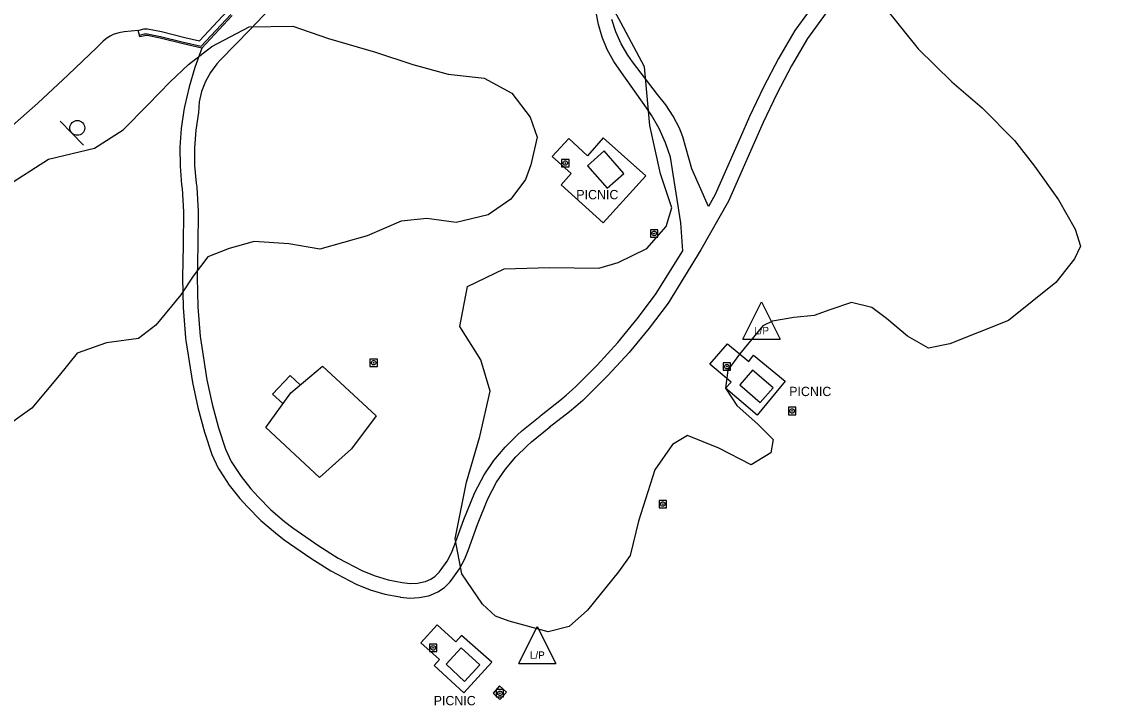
# Model space of a CAD drawing. Extents: x 2161152 to 2175754, y 602179 to 617749.
# Drawn here: x 2163221.4 to 2163512.2, y 604952.2 to 605136.2 of the extents above; entities that cross this region are included whole.
import ezdxf

# ---------------------------------------------------------------- set-up
doc = ezdxf.new("R2010")
doc.units = 0
for name, color, linetype in [('RD_EX_Bldg', 7, 'Continuous'), ('RD_EX_BldgApp_Sign', 7, 'Continuous'), ('RD_EX_Conc_Curb', 7, 'Continuous'), ('RD_EX_Conc_Gutter', 7, 'Continuous'), ('RD_EX_Conc_Sidewalk', 7, 'Continuous'), ('RD_EX_Conc_Slab', 7, 'Continuous'), ('RD_EX_Misc', 7, 'Continuous'), ('RD_EX_Misc_Golf_Cartpath', 7, 'Continuous'), ('RD_EX_Parking_Conc', 7, 'Continuous'), ('RD_EX_UT', 7, 'Continuous'), ('RD_EX_VEG', 7, 'Continuous')]:
    doc.layers.add(name, color=color, linetype=linetype)

msp = doc.modelspace()

# ---------------------------------------------------------------- linework, layer by layer
at = {"layer": 'RD_EX_Bldg'}
msp.add_lwpolyline([(2163287.04, 605026.92), (2163293.79, 605036.25), (2163302.3, 605043.44), (2163316.78, 605030.11), (2163310.1, 605021.2), (2163301.49, 605013.52), (2163287.04, 605026.92)], dxfattribs=at)
at = {"layer": 'RD_EX_BldgApp_Sign'}
msp.add_line((2163231.72, 605109.37), (2163238.02, 605102.94), dxfattribs=at)
msp.add_circle((2163236.33, 605107.56), 2, dxfattribs=at)
at = {"layer": 'RD_EX_Conc_Curb'}
msp.add_lwpolyline([(2163278.03, 605137.76), (2163269.88, 605128.99), (2163264.84, 605130.15), (2163258.62, 605131.69), (2163255.13, 605132.39), (2163254.52, 605132.36), (2163253.17, 605132.03), (2163253.08, 605132.37), (2163253.04, 605132.51), (2163254.45, 605132.86), (2163255.17, 605132.89), (2163258.73, 605132.18), (2163264.96, 605130.64), (2163269.71, 605129.54), (2163277.67, 605138.1)], dxfattribs=at)
at = {"layer": 'RD_EX_Conc_Gutter'}
msp.add_lwpolyline([(2163253.04, 605132.51), (2163252.72, 605133.8), (2163254.26, 605134.18), (2163255.27, 605134.22), (2163259.02, 605133.47), (2163265.26, 605131.92), (2163269.26, 605131), (2163276.7, 605139.01)], dxfattribs=at)
at = {"layer": 'RD_EX_Conc_Sidewalk'}
for points in [[(2163516.51, 605215.95), (2163502.01, 605201.03), (2163482.15, 605182.07), (2163472.54, 605173.28), (2163460.21, 605161.95), (2163451.16, 605154.25), (2163443.84, 605146.23), (2163440.01, 605141.47), (2163432.82, 605131.59), (2163428.58, 605124.3), (2163424.57, 605116.72), (2163420.88, 605108.97), (2163418.49, 605103.5), (2163411.61, 605087.8), (2163404.18, 605074.72), (2163395.32, 605060.43), (2163390.19, 605053.63), (2163384.82, 605047.15), (2163379.14, 605040.92), (2163373.21, 605034.99), (2163372.35, 605034.17), (2163370.53, 605032.61), (2163368.78, 605031.12), (2163363.32, 605026.93)], [(2163298.9, 605151.01), (2163282.84, 605134.04), (2163274.87, 605125.86), (2163273.89, 605124.79), (2163272.18, 605122.5), (2163270.81, 605120), (2163269.8, 605117.33), (2163269.16, 605114.55), (2163268.91, 605111.71), (2163268.21, 605106.95), (2163267.88, 605102.22), (2163267.92, 605097.48), (2163268.32, 605092.7), (2163268.46, 605091.65), (2163268.85, 605085.1), (2163268.77, 605075.96), (2163268.59, 605067.32), (2163268.8, 605059.4), (2163269.39, 605051.44), (2163269.45, 605050.9), (2163271.23, 605039.73), (2163272.59, 605033.24), (2163274.32, 605026.84), (2163276.2, 605021.15), (2163277.77, 605017.84), (2163278.1, 605017.25), (2163280.43, 605013.73), (2163283.07, 605010.4), (2163284.98, 605008.32), (2163288.45, 605004.83), (2163292.14, 605001.63), (2163294.37, 604999.92), (2163301.31, 604995.08), (2163306.51, 604991.82), (2163313.05, 604988.39), (2163316.47, 604987.01), (2163320.02, 604985.96), (2163323.75, 604985.23), (2163323.79, 604985.22), (2163325.95, 604984.98), (2163327.9, 604985.07), (2163329.92, 604985.48), (2163330.05, 604985.52), (2163331.46, 604986.14), (2163332.64, 604986.96), (2163333.71, 604988.03), (2163334.23, 604988.73), (2163335.85, 604990.98), (2163337.07, 604993.26), (2163337.86, 604995.25), (2163340.39, 605002.22), (2163343.29, 605009.43), (2163345.81, 605014.23), (2163348.47, 605018.1), (2163351.45, 605021.67), (2163354.69, 605024.91), (2163356.01, 605026.07), (2163360.9, 605030.03), (2163361.19, 605030.25), (2163366.16, 605034.18), (2163367.9, 605035.68), (2163369.64, 605037.17), (2163370.4, 605037.88), (2163376.22, 605043.71), (2163381.77, 605049.8), (2163387.03, 605056.14), (2163391.98, 605062.71), (2163399.3, 605074.51), (2163398.74, 605082.04), (2163396.01, 605099.66), (2163394.66, 605103.58), (2163392.94, 605107.37), (2163390.88, 605110.97), (2163389.53, 605112.96), (2163382.77, 605122.44), (2163380.71, 605125.43), (2163378.97, 605128.62), (2163377.59, 605131.96), (2163376.58, 605135.41), (2163375.17, 605142.89)], [(2163436.78, 605143.89), (2163429.43, 605133.8), (2163425.05, 605126.26), (2163420.97, 605118.54), (2163417.2, 605110.65), (2163414.79, 605105.11), (2163408, 605089.61), (2163406.17, 605086.4), (2163401.7, 605096.57), (2163399.31, 605105.14), (2163398.37, 605107.51), (2163396.73, 605110.74), (2163394.75, 605113.77), (2163392.46, 605116.57), (2163385.76, 605125.31), (2163384.46, 605127.14), (2163382.68, 605130.18), (2163381.24, 605133.39), (2163380.18, 605136.72)], [(2163269.88, 605128.99), (2163267.99, 605123.84), (2163266.43, 605118.6), (2163265.21, 605113.27), (2163265.03, 605112.36), (2163264.3, 605107.37), (2163263.95, 605102.34), (2163263.99, 605097.29), (2163264.42, 605092.28), (2163264.55, 605091.27), (2163264.92, 605085), (2163264.84, 605076.02), (2163264.66, 605067.31), (2163264.87, 605059.2), (2163265.48, 605051.09), (2163265.55, 605050.39), (2163267.36, 605039.02), (2163268.77, 605032.32), (2163270.55, 605025.72), (2163272.54, 605019.69), (2163274.28, 605016.04), (2163274.74, 605015.21), (2163277.25, 605011.42), (2163280.08, 605007.85), (2163282.14, 605005.61), (2163285.76, 605001.96), (2163289.65, 604998.58), (2163292.05, 604996.75), (2163299.14, 604991.8), (2163304.55, 604988.41), (2163311.4, 604984.82), (2163315.17, 604983.3), (2163319.08, 604982.14), (2163323.09, 604981.35), (2163323.3, 604981.32), (2163325.83, 604981.05), (2163328.37, 604981.16), (2163330.87, 604981.66), (2163331.42, 604981.82), (2163333.39, 604982.7), (2163335.16, 604983.93), (2163336.69, 604985.45), (2163337.4, 604986.41), (2163339.19, 604988.9), (2163340.64, 604991.6), (2163341.53, 604993.85), (2163344.06, 605000.82), (2163346.86, 605007.78), (2163349.18, 605012.2), (2163351.6, 605015.73), (2163354.35, 605019.02), (2163357.38, 605022.04), (2163358.54, 605023.06), (2163363.32, 605026.93), (2163363.56, 605027.12)]]:
    msp.add_lwpolyline(points, dxfattribs=at)
at = {"layer": 'RD_EX_Conc_Slab'}
for points in [[(2163364.17, 605099.84), (2163369.26, 605095.26), (2163366.59, 605092.27), (2163377.88, 605081.99), (2163389.35, 605094.62), (2163377.89, 605104.85), (2163373.62, 605100.07), (2163368.6, 605104.72), (2163364.17, 605099.84)], [(2163418.35, 605046.43), (2163426.85, 605039.37), (2163419.26, 605030.25), (2163410.82, 605037.55), (2163412.31, 605039.17), (2163406.58, 605044), (2163411.35, 605049.5), (2163417.05, 605044.68), (2163418.35, 605046.43)], [(2163291.69, 605033.36), (2163288.89, 605035.91), (2163293.58, 605040.92), (2163296.32, 605038.39)], [(2163328.75, 604969.02), (2163333.82, 604964.54), (2163332.4, 604962.93), (2163340.32, 604955.59), (2163347.85, 604963.76), (2163339.71, 604971.01), (2163338.2, 604969.29), (2163333.17, 604973.81), (2163328.75, 604969.02)], [(2163348.22, 604955.49), (2163350.09, 604953.79), (2163351.82, 604955.7), (2163349.96, 604957.47), (2163348.22, 604955.49)]]:
    msp.add_lwpolyline(points, dxfattribs=at)
at = {"layer": 'RD_EX_Misc'}
for points in [[(2163366.67, 605097.1), (2163368.67, 605097.1), (2163368.67, 605099.1), (2163366.67, 605099.1), (2163366.67, 605097.1)], [(2163373.67, 605097.36), (2163378.93, 605091.38), (2163383.45, 605095.3), (2163378.1, 605101.38), (2163373.67, 605097.36)], [(2163367.07, 605098.1), (2163367.09, 605098.25), (2163367.15, 605098.39), (2163367.24, 605098.52), (2163367.36, 605098.61), (2163367.5, 605098.67), (2163367.66, 605098.7), (2163367.81, 605098.68), (2163367.95, 605098.63), (2163368.08, 605098.54), (2163368.18, 605098.43), (2163368.24, 605098.29), (2163368.27, 605098.14), (2163368.27, 605098.1)], [(2163368.27, 605098.1), (2163368.25, 605097.95), (2163368.2, 605097.8), (2163368.11, 605097.68), (2163367.99, 605097.59), (2163367.85, 605097.52), (2163367.69, 605097.5), (2163367.54, 605097.51), (2163367.4, 605097.57), (2163367.27, 605097.65), (2163367.17, 605097.77), (2163367.1, 605097.91), (2163367.08, 605098.06), (2163367.07, 605098.1)], [(2163367.57, 605098.1), (2163367.59, 605098.16), (2163367.64, 605098.19), (2163367.71, 605098.19), (2163367.76, 605098.16), (2163367.77, 605098.1)], [(2163367.77, 605098.1), (2163367.76, 605098.04), (2163367.71, 605098), (2163367.64, 605098), (2163367.59, 605098.04), (2163367.57, 605098.1)], [(2163390.59, 605078.15), (2163392.59, 605078.15), (2163392.59, 605080.15), (2163390.59, 605080.15), (2163390.59, 605078.15)], [(2163390.99, 605079.15), (2163391.01, 605079.31), (2163391.07, 605079.45), (2163391.16, 605079.57), (2163391.28, 605079.67), (2163391.42, 605079.73), (2163391.58, 605079.75), (2163391.73, 605079.74), (2163391.87, 605079.69), (2163392, 605079.6), (2163392.1, 605079.48), (2163392.16, 605079.34), (2163392.19, 605079.19), (2163392.19, 605079.15)], [(2163392.19, 605079.15), (2163392.17, 605079), (2163392.12, 605078.86), (2163392.03, 605078.74), (2163391.91, 605078.64), (2163391.77, 605078.58), (2163391.61, 605078.55), (2163391.46, 605078.57), (2163391.32, 605078.62), (2163391.19, 605078.71), (2163391.09, 605078.83), (2163391.02, 605078.96), (2163391, 605079.12), (2163390.99, 605079.15)], [(2163391.49, 605079.15), (2163391.51, 605079.21), (2163391.56, 605079.25), (2163391.63, 605079.25), (2163391.68, 605079.21), (2163391.69, 605079.15)], [(2163391.69, 605079.15), (2163391.68, 605079.09), (2163391.63, 605079.06), (2163391.56, 605079.06), (2163391.51, 605079.09), (2163391.49, 605079.15)], [(2163315.1, 605043.37), (2163317.1, 605043.37), (2163317.1, 605045.37), (2163315.1, 605045.37), (2163315.1, 605043.37)], [(2163315.5, 605044.37), (2163315.52, 605044.53), (2163315.57, 605044.67), (2163315.67, 605044.79), (2163315.79, 605044.89), (2163315.93, 605044.95), (2163316.08, 605044.97), (2163316.23, 605044.96), (2163316.38, 605044.91), (2163316.5, 605044.82), (2163316.6, 605044.7), (2163316.67, 605044.56), (2163316.7, 605044.41), (2163316.7, 605044.37)], [(2163316.7, 605044.37), (2163316.68, 605044.22), (2163316.62, 605044.08), (2163316.53, 605043.96), (2163316.41, 605043.86), (2163316.27, 605043.8), (2163316.12, 605043.77), (2163315.96, 605043.79), (2163315.82, 605043.84), (2163315.69, 605043.93), (2163315.59, 605044.05), (2163315.53, 605044.19), (2163315.5, 605044.34), (2163315.5, 605044.37)], [(2163316, 605044.37), (2163316.02, 605044.43), (2163316.07, 605044.47), (2163316.13, 605044.47), (2163316.18, 605044.43), (2163316.2, 605044.37)], [(2163316.2, 605044.37), (2163316.18, 605044.32), (2163316.13, 605044.28), (2163316.07, 605044.28), (2163316.02, 605044.32), (2163316, 605044.37)], [(2163410.11, 605042.34), (2163412.11, 605042.34), (2163412.11, 605044.34), (2163410.11, 605044.34), (2163410.11, 605042.34)], [(2163410.51, 605043.34), (2163410.53, 605043.49), (2163410.59, 605043.63), (2163410.68, 605043.76), (2163410.8, 605043.85), (2163410.94, 605043.92), (2163411.09, 605043.94), (2163411.24, 605043.93), (2163411.39, 605043.87), (2163411.51, 605043.78), (2163411.61, 605043.67), (2163411.68, 605043.53), (2163411.71, 605043.38), (2163411.71, 605043.34)], [(2163411.71, 605043.34), (2163411.69, 605043.19), (2163411.63, 605043.05), (2163411.54, 605042.92), (2163411.42, 605042.83), (2163411.28, 605042.77), (2163411.13, 605042.74), (2163410.97, 605042.76), (2163410.83, 605042.81), (2163410.7, 605042.9), (2163410.61, 605043.01), (2163410.54, 605043.15), (2163410.51, 605043.3), (2163410.51, 605043.34)], [(2163411.01, 605043.34), (2163411.03, 605043.4), (2163411.08, 605043.44), (2163411.14, 605043.44), (2163411.19, 605043.4), (2163411.21, 605043.34)], [(2163411.21, 605043.34), (2163411.19, 605043.28), (2163411.14, 605043.25), (2163411.08, 605043.25), (2163411.03, 605043.28), (2163411.01, 605043.34)], [(2163414.59, 605038.42), (2163420.09, 605033.64), (2163423.57, 605037.66), (2163418.05, 605042.38), (2163414.59, 605038.42)], [(2163427.71, 605030.39), (2163429.71, 605030.39), (2163429.71, 605032.39), (2163427.71, 605032.39), (2163427.71, 605030.39)], [(2163428.11, 605031.39), (2163428.13, 605031.54), (2163428.19, 605031.69), (2163428.28, 605031.81), (2163428.4, 605031.9), (2163428.54, 605031.97), (2163428.7, 605031.99), (2163428.85, 605031.98), (2163428.99, 605031.92), (2163429.12, 605031.84), (2163429.22, 605031.72), (2163429.28, 605031.58), (2163429.31, 605031.43), (2163429.31, 605031.39)], [(2163429.31, 605031.39), (2163429.29, 605031.24), (2163429.24, 605031.1), (2163429.14, 605030.97), (2163429.02, 605030.88), (2163428.88, 605030.82), (2163428.73, 605030.79), (2163428.58, 605030.81), (2163428.44, 605030.86), (2163428.31, 605030.95), (2163428.21, 605031.06), (2163428.14, 605031.2), (2163428.12, 605031.35), (2163428.11, 605031.39)], [(2163428.61, 605031.39), (2163428.63, 605031.45), (2163428.68, 605031.49), (2163428.75, 605031.49), (2163428.79, 605031.45), (2163428.81, 605031.39)], [(2163428.81, 605031.39), (2163428.79, 605031.33), (2163428.75, 605031.3), (2163428.68, 605031.3), (2163428.63, 605031.33), (2163428.61, 605031.39)], [(2163392.91, 605005.34), (2163394.91, 605005.34), (2163394.91, 605007.34), (2163392.91, 605007.34), (2163392.91, 605005.34)], [(2163393.31, 605006.34), (2163393.33, 605006.49), (2163393.38, 605006.64), (2163393.48, 605006.76), (2163393.6, 605006.85), (2163393.74, 605006.92), (2163393.89, 605006.94), (2163394.04, 605006.93), (2163394.18, 605006.87), (2163394.31, 605006.79), (2163394.41, 605006.67), (2163394.48, 605006.53), (2163394.51, 605006.38), (2163394.51, 605006.34)], [(2163394.51, 605006.34), (2163394.49, 605006.19), (2163394.43, 605006.05), (2163394.34, 605005.92), (2163394.22, 605005.83), (2163394.08, 605005.77), (2163393.93, 605005.74), (2163393.77, 605005.76), (2163393.63, 605005.81), (2163393.5, 605005.9), (2163393.4, 605006.01), (2163393.34, 605006.15), (2163393.31, 605006.3), (2163393.31, 605006.34)], [(2163393.81, 605006.34), (2163393.83, 605006.4), (2163393.88, 605006.44), (2163393.94, 605006.44), (2163393.99, 605006.4), (2163394.01, 605006.34)], [(2163394.01, 605006.34), (2163393.99, 605006.28), (2163393.94, 605006.25), (2163393.88, 605006.25), (2163393.83, 605006.28), (2163393.81, 605006.34)], [(2163331.1, 604966.65), (2163333.1, 604966.65), (2163333.1, 604968.65), (2163331.1, 604968.65), (2163331.1, 604966.65)], [(2163331.5, 604967.65), (2163331.52, 604967.8), (2163331.58, 604967.94), (2163331.67, 604968.07), (2163331.79, 604968.16), (2163331.93, 604968.22), (2163332.09, 604968.25), (2163332.24, 604968.23), (2163332.38, 604968.18), (2163332.51, 604968.09), (2163332.61, 604967.98), (2163332.67, 604967.84), (2163332.7, 604967.69), (2163332.7, 604967.65)], [(2163332.7, 604967.65), (2163332.68, 604967.5), (2163332.63, 604967.36), (2163332.54, 604967.23), (2163332.42, 604967.14), (2163332.28, 604967.07), (2163332.12, 604967.05), (2163331.97, 604967.06), (2163331.83, 604967.12), (2163331.7, 604967.21), (2163331.6, 604967.32), (2163331.53, 604967.46), (2163331.51, 604967.61), (2163331.5, 604967.65)], [(2163332, 604967.65), (2163332.02, 604967.71), (2163332.07, 604967.74), (2163332.14, 604967.74), (2163332.19, 604967.71), (2163332.2, 604967.65)], [(2163332.2, 604967.65), (2163332.19, 604967.59), (2163332.14, 604967.55), (2163332.07, 604967.55), (2163332.02, 604967.59), (2163332, 604967.65)], [(2163335.61, 604963.24), (2163340.52, 604958.61), (2163344.63, 604963.09), (2163339.61, 604967.64), (2163335.61, 604963.24)], [(2163349.05, 604954.44), (2163351.05, 604954.44), (2163351.05, 604956.44), (2163349.05, 604956.44), (2163349.05, 604954.44)], [(2163349.45, 604955.44), (2163349.47, 604955.59), (2163349.53, 604955.73), (2163349.62, 604955.85), (2163349.74, 604955.95), (2163349.88, 604956.01), (2163350.03, 604956.04), (2163350.19, 604956.02), (2163350.33, 604955.97), (2163350.46, 604955.88), (2163350.56, 604955.76), (2163350.62, 604955.63), (2163350.65, 604955.48), (2163350.65, 604955.44)], [(2163350.65, 604955.44), (2163350.63, 604955.29), (2163350.58, 604955.14), (2163350.48, 604955.02), (2163350.36, 604954.92), (2163350.22, 604954.86), (2163350.07, 604954.84), (2163349.92, 604954.85), (2163349.78, 604954.91), (2163349.65, 604954.99), (2163349.55, 604955.11), (2163349.48, 604955.25), (2163349.45, 604955.4), (2163349.45, 604955.44)], [(2163349.95, 604955.44), (2163349.97, 604955.5), (2163350.02, 604955.53), (2163350.08, 604955.53), (2163350.13, 604955.5), (2163350.15, 604955.44)], [(2163350.15, 604955.44), (2163350.13, 604955.38), (2163350.08, 604955.34), (2163350.02, 604955.34), (2163349.97, 604955.38), (2163349.95, 604955.44)]]:
    msp.add_lwpolyline(points, dxfattribs=at)
at = {"layer": 'RD_EX_Parking_Conc'}
msp.add_lwpolyline([(2163252.72, 605133.8), (2163248.98, 605133.38), (2163247.52, 605133.13), (2163245.96, 605132.66), (2163245.18, 605132.26), (2163244.24, 605131.66), (2163243.32, 605130.9), (2163241.62, 605129.19), (2163233.89, 605121.8), (2163225.68, 605114.18), (2163216.55, 605106.12)], dxfattribs=at)
at = {"layer": 'RD_EX_UT'}
for p, q in [((2163415.48, 605050.75), (2163420.48, 605060.75)), ((2163420.48, 605060.75), (2163425.48, 605050.75)), ((2163415.48, 605050.75), (2163425.48, 605050.75)), ((2163355.12, 604963.42), (2163360.12, 604973.42)), ((2163360.12, 604973.42), (2163365.12, 604963.42)), ((2163355.12, 604963.42), (2163365.12, 604963.42))]:
    msp.add_line(p, q, dxfattribs=at)
at = {"layer": 'RD_EX_VEG'}
for points in [[(2163453.12, 605140.65), (2163462.6, 605128.83), (2163471.67, 605119.98), (2163479.88, 605112.92), (2163488.52, 605104.2), (2163493.95, 605097.24), (2163500.39, 605088.24), (2163504.87, 605080.31), (2163506.34, 605075.74), (2163504.74, 605072.29), (2163499.64, 605066), (2163486.93, 605055.75), (2163471.14, 605049.46)], [(2163471.14, 605049.46), (2163465.43, 605048.33), (2163459.78, 605051.49), (2163454.1, 605056.26), (2163450.16, 605059.25), (2163444.65, 605060.61), (2163438.84, 605058.64), (2163434.62, 605057.12), (2163429.15, 605056.51), (2163423.42, 605055.58), (2163420.85, 605054.27), (2163414.56, 605046.65), (2163411.41, 605042.41), (2163410.8, 605037.52), (2163413.84, 605032.87), (2163419.59, 605027.79), (2163423.57, 605023.72), (2163422.96, 605020.1), (2163417.72, 605016.89), (2163409.01, 605021.4), (2163400.53, 605024.8), (2163396.47, 605022.39), (2163391.74, 605015.56), (2163387.34, 605001.75), (2163385.14, 604992.46), (2163382.02, 604988.11), (2163373.66, 604977.79), (2163368.7, 604973.42), (2163363.06, 604971.98), (2163352.54, 604974.86), (2163348.86, 604976.16), (2163345.36, 604979.41), (2163339.82, 604987.58), (2163338, 604997.02), (2163341.1, 605012.21), (2163344.69, 605024.51), (2163347.47, 605036.73), (2163344.97, 605045.15), (2163339.3, 605054.1), (2163341.31, 605064.84), (2163351.23, 605069.64), (2163363.42, 605069.96), (2163376.68, 605069.79), (2163381.9, 605071.36), (2163389.64, 605075.07), (2163394.84, 605081.01), (2163396.37, 605086.03), (2163393.24, 605095.21), (2163390.45, 605108.21), (2163388.98, 605124.02), (2163382.59, 605135.88), (2163380.96, 605138.88)], [(2163216.84, 605091.61), (2163228.56, 605099.13), (2163240.96, 605102.13), (2163248.66, 605107.03), (2163255.41, 605113.88), (2163261.3, 605119.98), (2163266.3, 605124.64), (2163272.57, 605129.46), (2163282.59, 605134.76), (2163294.34, 605134.9), (2163303.92, 605131.65), (2163316.61, 605127.97), (2163326.62, 605124.66), (2163336.1, 605121.99), (2163345.86, 605120.92), (2163353.24, 605116.92), (2163358.24, 605110.45), (2163360.05, 605105.07), (2163358.39, 605097.59), (2163356.98, 605093.64), (2163353.04, 605088.34), (2163346.9, 605084.17), (2163338.29, 605082.13), (2163330.42, 605083.19), (2163323.45, 605082.5), (2163314.35, 605078.51)], [(2163314.35, 605078.51), (2163301.59, 605074.95), (2163293.23, 605076.36), (2163283.92, 605077.03), (2163277.19, 605075.14), (2163271.48, 605072.88), (2163267.5, 605067.69), (2163264.18, 605062.6), (2163257.51, 605054.48), (2163252.85, 605050.89), (2163244.22, 605049.74), (2163236.31, 605046.96), (2163231.46, 605040.95), (2163224.08, 605032.16), (2163215.55, 605026.02)]]:
    msp.add_lwpolyline(points, dxfattribs=at)

# ---------------------------------------------------------------- texts
at = {"layer": 'RD_EX_Misc_Golf_Cartpath'}
for p in [(2163370.63, 605088.36), (2163427.92, 605035.4), (2163332.24, 604952.21)]:
    msp.add_text('PICNIC', height=2.5, dxfattribs=at).set_placement(p)
at = {"layer": 'RD_EX_UT'}
for p in [(2163418.47, 605052.03), (2163358.12, 604964.7)]:
    msp.add_text('L/P', height=2, dxfattribs=at).set_placement(p)

doc.saveas('drawing.dxf')
